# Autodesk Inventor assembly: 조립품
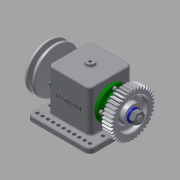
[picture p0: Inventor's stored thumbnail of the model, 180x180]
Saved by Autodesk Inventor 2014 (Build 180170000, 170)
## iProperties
Created: 2018-11
Part Number: 조립품
Document SubType Name: Assembly
Designer: kh
Author: kh
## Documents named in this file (13)
- C:\Users\kh\Desktop\481107V1024\조립품.iam
- C:\Users\kh\Desktop\481107V1024\본체.ipt
- C:\Users\kh\Desktop\481107V1024\V벨트풀리.ipt
- C:\Users\kh\Desktop\481107V1024\너트 M12x1.25.ipt
- C:\Users\kh\Desktop\481107V1024\베어링 6203.ipt
- C:\Users\kh\Desktop\481107V1024\볼트 M4.ipt
- C:\Users\kh\Desktop\481107V1024\부시.ipt
- C:\Users\kh\Desktop\481107V1024\스퍼기어.ipt
- C:\Users\kh\Desktop\481107V1024\오일 실 26 38 8.ipt
- C:\Users\kh\Desktop\481107V1024\와셔 12x24.ipt
- C:\Users\kh\Desktop\481107V1024\축.ipt
- C:\Users\kh\Desktop\481107V1024\커버.ipt
- C:\Users\kh\Desktop\481107V1024\키 5x5x12.ipt
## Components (1 placed, 1 different names)
1. V벨트풀리:1
